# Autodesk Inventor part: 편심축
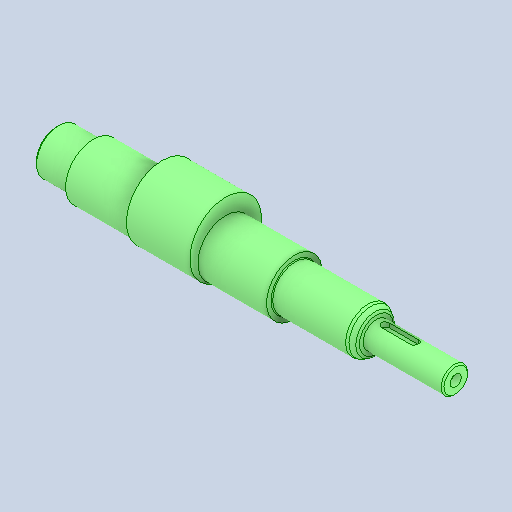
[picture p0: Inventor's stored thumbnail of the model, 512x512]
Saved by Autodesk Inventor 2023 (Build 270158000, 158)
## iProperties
Created: 2024-09
Part Number: 편심축
Material: 강철, 탄소
Document SubType Name: Modeling
Designer: home
Density: 7.85 g/cm^3
Appearance: 기본값
Author: jhkim
Sending System: Autodesk Inventor 2025
Preprocessor: ST-DEVELOPER v20
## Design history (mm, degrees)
feature "솔리드1"
node "솔리드2"
